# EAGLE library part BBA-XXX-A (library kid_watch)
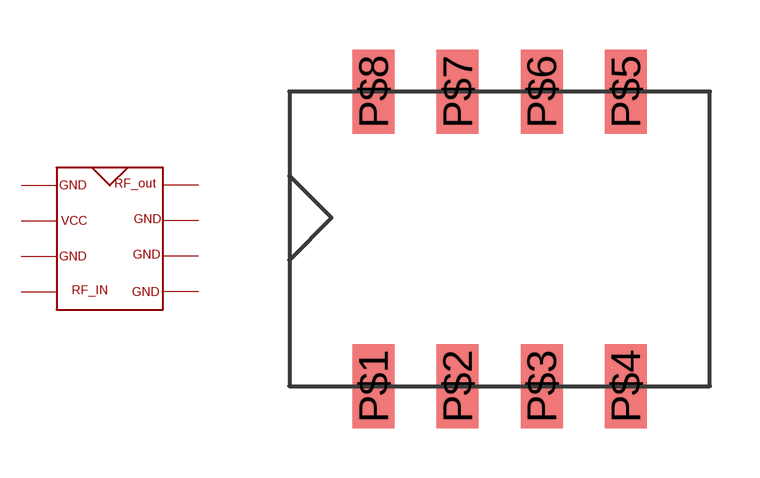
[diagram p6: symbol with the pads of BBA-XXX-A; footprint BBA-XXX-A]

Designator prefix -

## BBA-XXX-A  [BBA-XXX-A]
P$1  P$1
P$2  P$2
P$3  P$3
P$4  P$4
P$5  P$5
P$6  P$6
P$7  P$7
P$8  P$8

## Footprint BBA-XXX-A (pad centres in mm)
smd 1.27 x 2.54: P$1 0,0; P$2 2.54,0; P$3 5.08,0; P$4 7.62,0; P$5 7.62,8.89; P$6 5.08,8.89; P$7 2.54,8.89; P$8 0,8.89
